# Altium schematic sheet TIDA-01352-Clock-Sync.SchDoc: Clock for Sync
size 431 x 279 mm; Date: Not shown in title block; ApprovedBy: Not shown in title block; CheckedBy: Not shown in title block; Author: Not shown in title block; CompanyName: Not shown in title block; DrawnBy: Sanjay Pithadia; Engineer: Sanjay Pithadia; Organization: Not shown in title block; Address1: Not shown in title block; Address2: Not shown in title block; Address3: Not shown in title block; Address4: Not shown in title block; DocumentNumber: 1; Revision: Use project parameter SCH_Rev; SheetNumber: 6; SheetTotal: 9; PageSetup: Record=PageOptions¦CenterHorizontal=True¦CenterVertical=True¦PrintScale=1.00¦XCorrection=1.00¦YCorrection=1.00¦PrintKind=0¦BorderSize=5000000¦LeftOffset=0¦BottomOffset=0¦Orientation=2¦PaperLength=1000¦PaperWidth=1000¦Scale=100¦PaperSource=15¦PrintQuality=600¦MediaType=1¦DitherType=10¦PaperKind=Letter¦PrintScaleMode=1
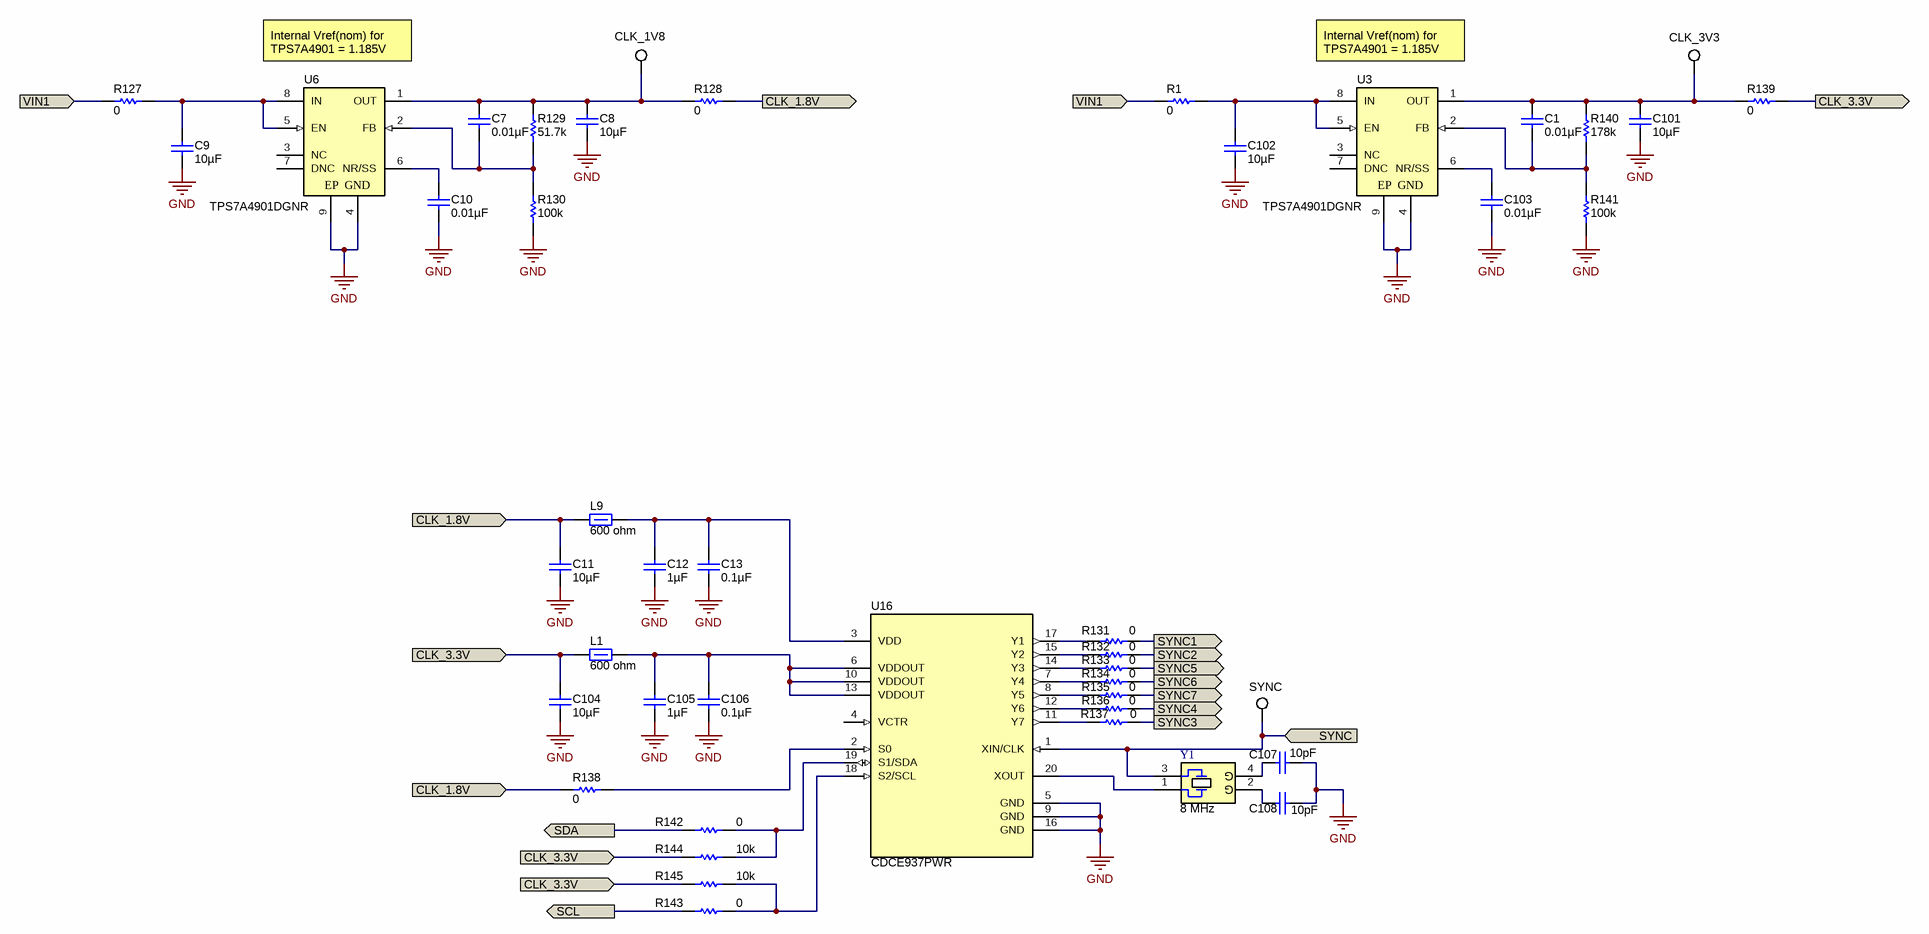
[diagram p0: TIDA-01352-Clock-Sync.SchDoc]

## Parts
C1  ValueDisplayed: 0.01µF  [0603]  (hidden comment: GRM188R71H103KA01D)
C7  ValueDisplayed: 0.01µF  [0603]  (hidden comment: GRM188R71H103KA01D)
C8  ValueDisplayed: 10µF  [1206_180]  (hidden comment: C3216X5R1H106K160AB)
C9  ValueDisplayed: 10µF  [1206_180]  (hidden comment: C3216X5R1H106K160AB)
C10  ValueDisplayed: 0.01µF  [0603]  (hidden comment: GRM188R71H103KA01D)
C11  ValueDisplayed: 10µF  [1206_180]  (hidden comment: C3216X5R1H106K160AB)
C12  ValueDisplayed: 1µF  [0603]  (hidden comment: C1608X5R1E105K080AC)
C13  ValueDisplayed: 0.1µF  [0603]  (hidden comment: C0603C104K5RACTU)
C101  ValueDisplayed: 10µF  [1206_180]  (hidden comment: C3216X5R1H106K160AB)
C102  ValueDisplayed: 10µF  [1206_180]  (hidden comment: C3216X5R1H106K160AB)
C103  ValueDisplayed: 0.01µF  [0603]  (hidden comment: GRM188R71H103KA01D)
C104  ValueDisplayed: 10µF  [1206_180]  (hidden comment: C3216X5R1H106K160AB)
C105  ValueDisplayed: 1µF  [0603]  (hidden comment: C1608X5R1E105K080AC)
C106  ValueDisplayed: 0.1µF  [0603]  (hidden comment: C0603C104K5RACTU)
C107  ValueDisplayed: 10pF  [0603]  (hidden comment: C0603C100F5GAC7867)
C108  ValueDisplayed: 10pF  [0603]  (hidden comment: C0603C100F5GAC7867)
CLK_1V8  5002  [Keystone5002]  (value not drawn)
CLK_3V3  5002  [Keystone5002]  (value not drawn)
L1  ValueDisplayed: 600 ohm  [0603]  (hidden comment: BLM18EG601SH1)
L9  ValueDisplayed: 600 ohm  [0603]  (hidden comment: BLM18EG601SH1)
R1  ValueDisplayed: 0  [0603]  (hidden comment: CRCW06030000Z0EA)
R127  ValueDisplayed: 0  [0603]  (hidden comment: CRCW06030000Z0EA)
R128  ValueDisplayed: 0  [0603]  (hidden comment: CRCW06030000Z0EA)
R129  ValueDisplayed: 51.7k  [0603]  (hidden comment: RT0603DRE0751K7L)
R130  ValueDisplayed: 100k  [0603]  (hidden comment: RC0603FR-07100KL)
R131  ValueDisplayed: 0  [0603]  (hidden comment: CRCW06030000Z0EA)
R132  ValueDisplayed: 0  [0603]  (hidden comment: CRCW06030000Z0EA)
R133  ValueDisplayed: 0  [0603]  (hidden comment: CRCW06030000Z0EA)
R134  ValueDisplayed: 0  [0603]  (hidden comment: CRCW06030000Z0EA)
R135  ValueDisplayed: 0  [0603]  (hidden comment: CRCW06030000Z0EA)
R136  ValueDisplayed: 0  [0603]  (hidden comment: CRCW06030000Z0EA)
R137  ValueDisplayed: 0  [0603]  (hidden comment: CRCW06030000Z0EA)
R138  ValueDisplayed: 0  [0603]  (hidden comment: CRCW06030000Z0EA)
R139  ValueDisplayed: 0  [0603]  (hidden comment: CRCW06030000Z0EA)
R140  ValueDisplayed: 178k  [0603]  (hidden comment: CRCW0603178KFKEA)
R141  ValueDisplayed: 100k  [0603]  (hidden comment: RC0603FR-07100KL)
R142  ValueDisplayed: 0  [0603]  (hidden comment: CRCW06030000Z0EA)
R143  ValueDisplayed: 0  [0603]  (hidden comment: CRCW06030000Z0EA)
R144  ValueDisplayed: 10k  [0603]  (hidden comment: RC0603JR-0710KL)
R145  ValueDisplayed: 10k  [0603]  (hidden comment: RC0603JR-0710KL)
SYNC  5002  [Keystone5002]  (value not drawn)
U3  TPS7A4901DGNR  [DGN0008D_N]
U6  TPS7A4901DGNR  [DGN0008D_N]
U16  CDCE937PWR  [PW0020A_N]
Y1  Frequency: 8 MHz  [CTS_406]  (hidden comment: 406I35D08M00000)

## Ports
CLK_1.8V (in), CLK_1.8V (out), CLK_3.3V (in), CLK_3.3V (out), SCL (out), SDA (out), SYNC1 (out), SYNC2 (out), SYNC3 (out), SYNC4 (out), SYNC5 (out), SYNC6 (out), SYNC7 (out), SYNC (in), VIN1 (in)

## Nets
GND: C8.2 C9.2 C10.1 C11.2 C12.2 C13.2 C101.2 C102.2 C103.1 C104.2 C105.2 C106.2 C107.1 C108.1 R130.2 R141.2 U3.4(GND) U3.9(EP) U6.4(GND) U6.9(EP) U16.5(GND) U16.9(GND) U16.16(GND)
CLK_1.8V: C11.1 L9.1 R128.1 R138.1 ; port CLK_1.8V
CLK_3.3V: C104.1 L1.1 R139.1 R144.1 R145.1 ; port CLK_3.3V
SCL: R143.1 ; port SCL
SDA: R142.1 ; port SDA
SYNC: SYNC.1 U16.1(XIN/CLK) Y1.3 ; port SYNC
SYNC1: R131.1 ; port SYNC1
SYNC2: R132.1 ; port SYNC2
SYNC3: R137.1 ; port SYNC3
SYNC4: R136.1 ; port SYNC4
SYNC5: R133.1 ; port SYNC5
SYNC6: R134.1 ; port SYNC6
SYNC7: R135.1 ; port SYNC7
VIN1: R1.2 R127.2 ; port VIN1
NetC1_1: C1.1 R140.2 R141.1 U3.2(FB)
NetC1_2: C1.2 C101.1 CLK_3V3.1 R139.2 R140.1 U3.1(OUT)
NetC7_1: C7.1 R129.2 R130.1 U6.2(FB)
NetC7_2: C7.2 C8.1 CLK_1V8.1 R128.2 R129.1 U6.1(OUT)
NetC9_1: C9.1 R127.1 U6.5(EN) U6.8(IN)
NetC10_2: C10.2 U6.6(NR/SS)
NetC12_1: C12.1 C13.1 L9.2 U16.3(VDD)
NetC102_1: C102.1 R1.1 U3.5(EN) U3.8(IN)
NetC103_2: C103.2 U3.6(NR/SS)
NetC105_1: C105.1 C106.1 L1.2 U16.6(VDDOUT) U16.10(VDDOUT) U16.13(VDDOUT)
NetC107_2: C107.2 Y1.4(GND)
NetC108_2: C108.2 Y1.2(GND)
NetR131_2: R131.2 U16.17(Y1)
NetR132_2: R132.2 U16.15(Y2)
NetR133_2: R133.2 U16.14(Y3)
NetR134_2: R134.2 U16.7(Y4)
NetR135_2: R135.2 U16.8(Y5)
NetR136_2: R136.2 U16.12(Y6)
NetR137_2: R137.2 U16.11(Y7)
NetR138_2: R138.2 U16.2(S0)
NetR142_2: R142.2 R144.2 U16.19(S1/SDA)
NetR143_2: R143.2 R145.2 U16.18(S2/SCL)
NetU16_20: U16.20(XOUT) Y1.1

Not connected (* = marked no-connect by the designer): U3 3(NC) 7(DNC); U6 3(NC) 7(DNC); U16 4(VCTR)

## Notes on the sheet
- (near U6) Internal Vref(nom) for TPS7A4901 = 1.185V
- (near U3) Internal Vref(nom) for TPS7A4901 = 1.185V

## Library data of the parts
C1 C7 C10 C103 = GRM188R71H103KA01D: CAP, CERM, 0.01 µF, 50 V, +/- 10%, X7R, 0603; Manufacturer: MuRata; Polarized: N; CompType: Capacitor; Value: 0.01uF; U/M: EA; Cap_F: 0.00000001; Tolerance_%: 10; Value1: Unknown; VDC_V: 50; Value2: 50V; TaMin_C: -55; TaMax_C: 125; SizeArea_mm2: 1.28; SizeAreaWB_mm2: 4.68; SizeX_mm: 1.6; SizeY_mm: 0.8; SizeZ_mm: 1; AEC Category: Q200
C8 C9 C11 C101 C102 C104 = C3216X5R1H106K160AB: CAP, CERM, 10 µF, 50 V, +/- 10%, X5R, 1206; Manufacturer: TDK; Polarized: N; CompType: Capacitor; Value: 10uF; U/M: EA; Cap_F: 0.00001; Tolerance_%: 10; ESR_ohm: 0.002229; Value1: 0.002229 ohm; VDC_V: 50; Value2: 50V; IRMS_A: 4.85932; TaMin_C: -55; TaMax_C: 85; SizeArea_mm2: 5.12; SizeAreaWB_mm2: 10.92; SizeX_mm: 3.2; SizeY_mm: 1.6; SizeZ_mm: 1.8; AEC Category: Q200
C12 C105 = C1608X5R1E105K080AC: CAP, CERM, 1 µF, 25 V, +/- 10%, X5R, 0603; Manufacturer: TDK; Polarized: N; CompType: Capacitor; Value: 1uF; U/M: EA; Cap_F: 0.000001; Tolerance_%: 10; Value1: Unknown; VDC_V: 25; Value2: 25V; TaMin_C: -55; TaMax_C: 85; SizeArea_mm2: 1.28; SizeAreaWB_mm2: 4.68; SizeX_mm: 1.6; SizeY_mm: 0.8; SizeZ_mm: 1; AEC Category: Q200
C13 C106 = C0603C104K5RACTU: CAP, CERM, 0.1 µF, 50 V, +/- 10%, X7R, 0603; Manufacturer: Kemet; Polarized: N; CompType: Capacitor; Value: 0.1uF; U/M: EA; Cap_F: 0.0000001; Tolerance_%: 10; Value1: Unknown; VDC_V: 50; Value2: 50V; TaMin_C: -55; TaMax_C: 125; SizeArea_mm2: 1.28; SizeAreaWB_mm2: 4.68; SizeX_mm: 1.6; SizeY_mm: 0.8; SizeZ_mm: 1; AEC Category: Q200
C107 C108 = C0603C100F5GAC7867: CAP, CERM, 10 pF, 50 V, +/- 1%, C0G/NP0, 0603; Manufacturer: Kemet; Polarized: N; CompType: Capacitor; Value: 10pF; U/M: EA; Cap_F: 0.00000000001; Tolerance_%: 1; Value1: Unknown; VDC_V: 50; Value2: 50V; TaMin_C: -55; TaMax_C: 125; SizeArea_mm2: 1.28; SizeAreaWB_mm2: 4.68; SizeX_mm: 1.6; SizeY_mm: 0.8; AEC Category: Q200
CLK_1V8 CLK_3V3 SYNC = 5002: Test Point, Miniature, White, TH; Manufacturer: Keystone; CompType: Test Point Loop; ContactFinish: Silver
L1 L9 = BLM18EG601SH1: Ferrite Bead, 600 ohm @ 100 MHz, 0.5 A, 0603; Manufacturer: MuRata; Value: 600 ohm; Imax_A: 0.5; DCR_ohm: 0.35; Value1: 0.35 ohm; Value2: 0.5A; SizeAreaWB_mm2: 4.68; SizeArea_mm2: 1.28; SizeX_mm: 1.6; SizeY_mm: 0.8; SizeZ_mm: 1; ZTyp@100MHz_Ohm: 600; Ztyp@1GHz_Ohm: 700
R1 R127 R128 R131-R139 R142 R143 = CRCW06030000Z0EA: RES, 0, 5%, 0.1 W, 0603; Manufacturer: Vishay-Dale; CompType: Resistor; Value: 0; Value_Code: 0000; Tolerance_%: 5; Power_W: 0.1; Value2: 0.1W; VDC_V: 75; TempCo: 200 ppm/C; SizeArea_mm2: 1.28; SizeX_mm: 1.6; SizeY_mm: 0.8; SizeZ_mm: 1; EIA_Code: E24; U/M: EA; AEC Category: Q200
R129 = RT0603DRE0751K7L: RES, 51.7 k, 0.5%, 0.1 W, 0603; Manufacturer: Yageo America; CompType: Resistor; Value: 51.7k; Res_ohm: 51700; Value_Code: 51k7; Tolerance_%: 0.5; Power_W: 0.1; Value2: 0.1W; VDC_V: 75; TempCo: 50 ppm/C; SizeArea_mm2: 1.28; SizeX_mm: 1.6; SizeY_mm: 0.8; SizeZ_mm: 1; EIA_Code: E192; U/M: EA; AEC Category: Q200
R130 R141 = RC0603FR-07100KL: RES, 100 k, 1%, 0.1 W, 0603; Manufacturer: Yageo America; CompType: Resistor; Value: 100k; Res_ohm: 100000; Tolerance_%: 1; Power_W: 0.1; Value2: 0.1W; VDC_V: 150; TempCo: 200 ppm/C; SizeArea_mm2: 1.28; SizeX_mm: 1.6; SizeY_mm: 0.8; EIA_Code: E96; U/M: EA; AEC Category: Q200
R140 = CRCW0603178KFKEA: RES, 178 k, 1%, 0.1 W, 0603; Manufacturer: Vishay-Dale; CompType: Resistor; Value: 178k; Res_ohm: 178000; Tolerance_%: 1; Power_W: 0.1; Value2: 0.1W; VDC_V: 75; TempCo: 100 ppm/C; SizeArea_mm2: 1.28; SizeX_mm: 1.6; SizeY_mm: 0.8; EIA_Code: E96; U/M: EA; AEC Category: Q200
R144 R145 = RC0603JR-0710KL: RES, 10 k, 5%, 0.1 W, 0603; Manufacturer: Yageo America; CompType: Resistor; Value: 10k; Res_ohm: 10000; Value_Code: 10k0; Tolerance_%: 5; Power_W: 0.1; Value2: 0.1W; VDC_V: 50; TempCo: 100 ppm/C; SizeArea_mm2: 1.28; SizeX_mm: 1.6; SizeY_mm: 0.8; SizeZ_mm: 1; EIA_Code: E24; U/M: EA; AEC Category: Q200
U3 U6 = TPS7A4901DGNR: Single Output High PSRR LDO, 150 mA, Adjustable 1.2 to 33 V Output, 3 to 36 V Input, with Ultra-Low Noise, 8-pin MSOP (DGN), -40 to 125 degC, Green (RoHS & no Sb/Br); Manufacturer: Texas Instruments; Alternate PartNumber: Equivalent; Accuracy(%): 1.5; Iout(Max)(A): 0.15; Iq(Typ)(mA): 0.06; Power Good: TRUE; SubFamily: Single Channel LDO; Vdo(Typ)(mV): 260; Vin(Max)(V): 36; Vin(Min)(V): 3; Vout Adj(Max)(V): 33; Vout Adj(Min)(V): 1.2
U16 = CDCE937PWR: Programmable 3-PLL VCXO Clock Synthesizer With 1.8-V, 2.5-V and 3.3-V LVCMOS Outputs, PW0020A (TSSOP-20); Manufacturer: Texas Instruments; SymbolCreator: Altium; SizeArea_mm2: 43.56; SizeAreaWB_mm2: 73.96; SizeX_mm: 6.6; SizeZ_mm: 1.2; CompType: IC; U/M: EA
Y1 = 406I35D08M00000: Crystal, 8 MHz, 18 pF, SMD; Manufacturer: CTS Electrocomponents; SymbolCreator: a0412235; U/M: EA; TaMin_C: -40; TaMax_C: 85; Frequency Stability: ±50ppm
